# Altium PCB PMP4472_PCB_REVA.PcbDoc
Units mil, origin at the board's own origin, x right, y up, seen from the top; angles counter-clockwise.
Board outline 3307.09 x 3307.09 mil, 2 copper layers (TOP, BOTTOM), stack 10.4 mil thick; 66 components, 41 nets, 173 pads, 20 vias.
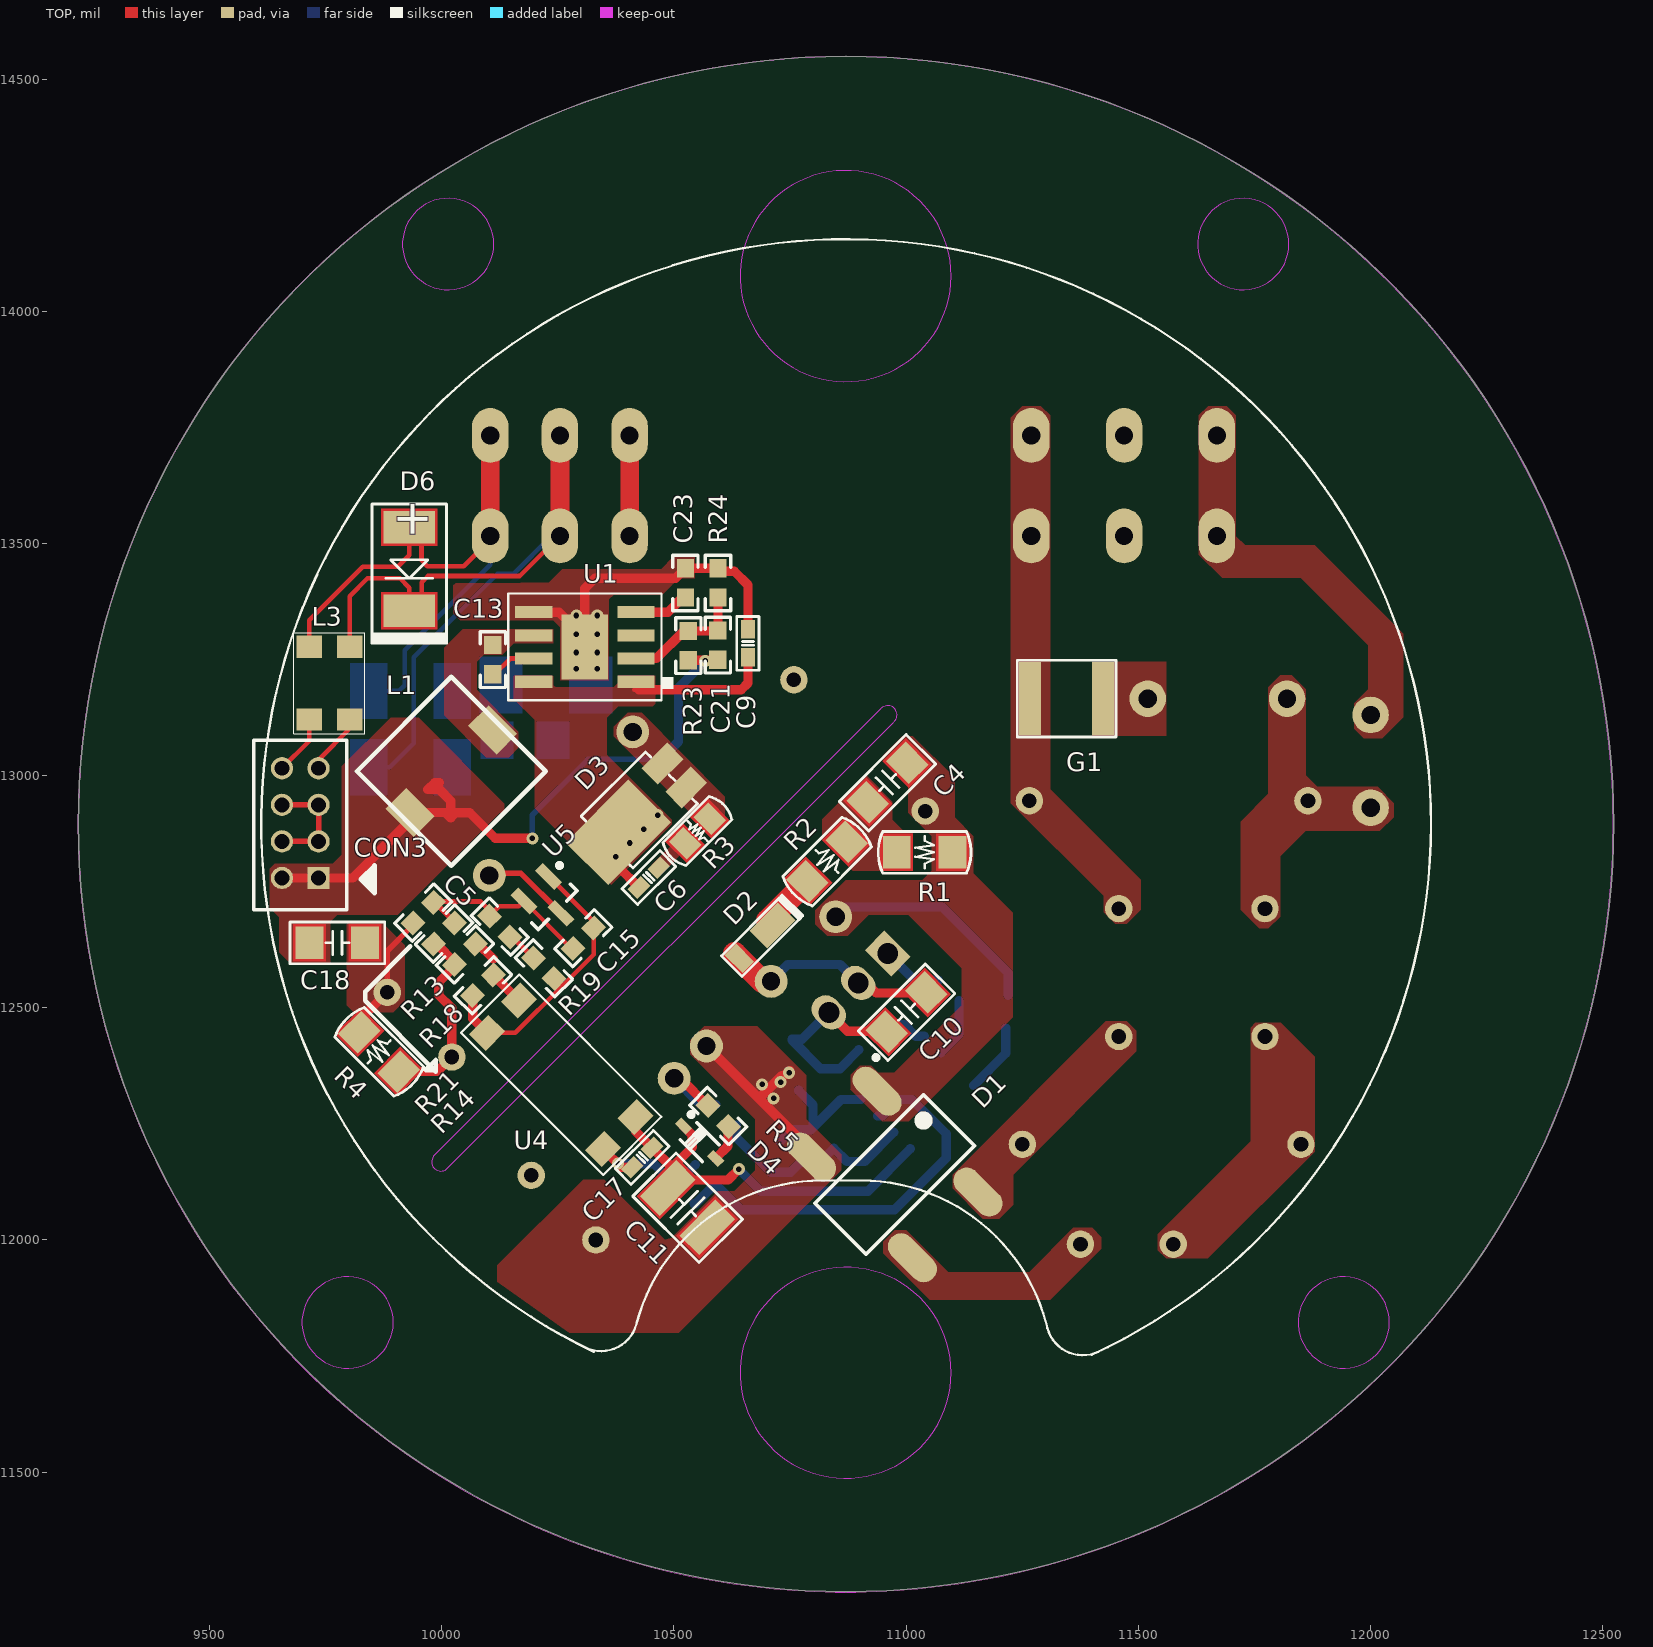
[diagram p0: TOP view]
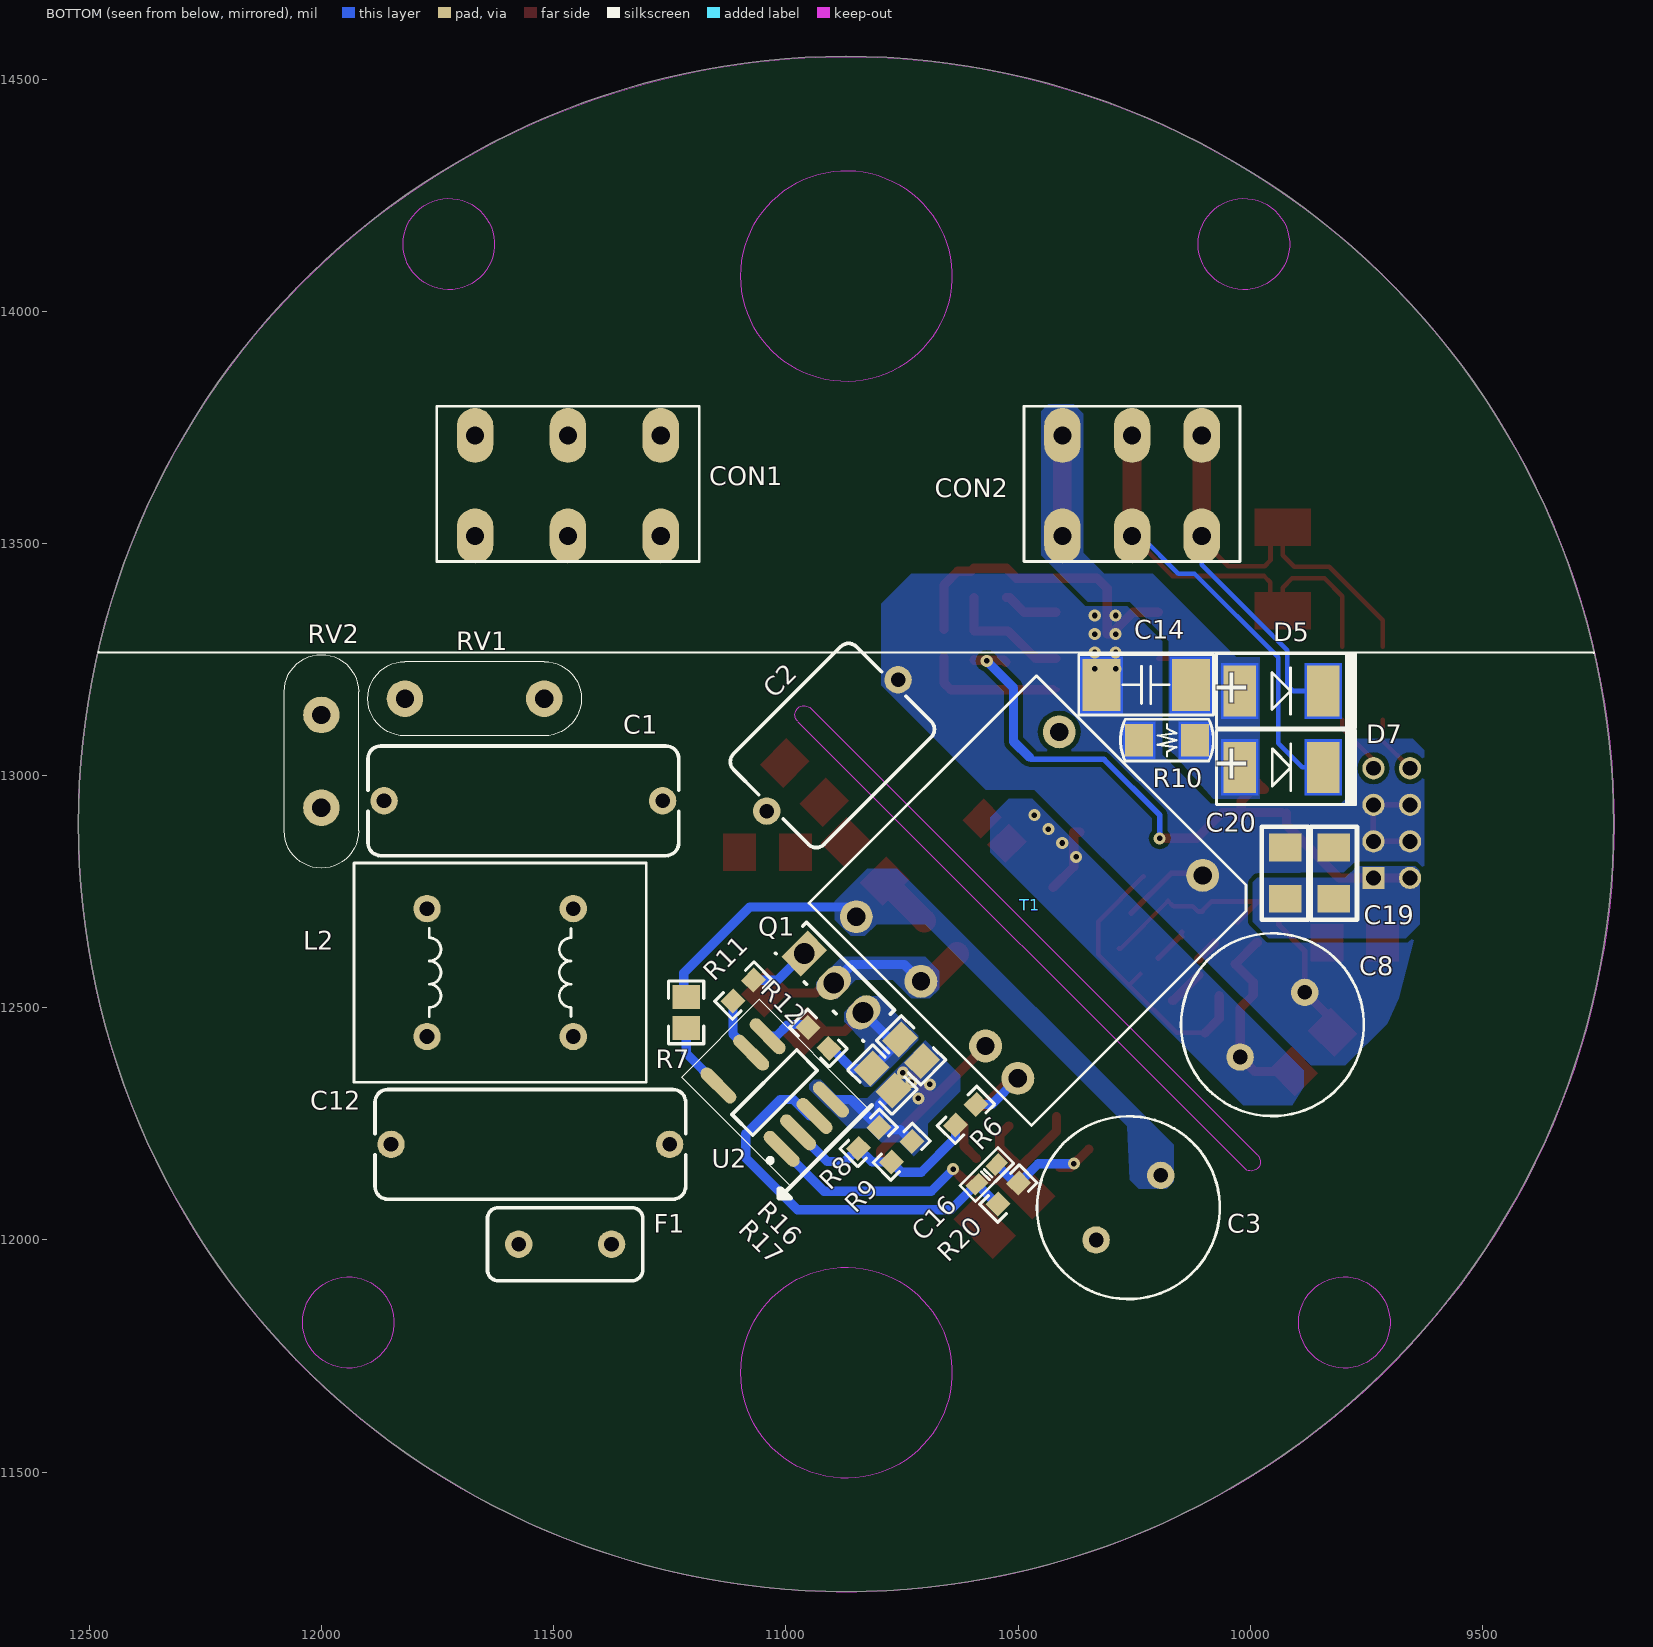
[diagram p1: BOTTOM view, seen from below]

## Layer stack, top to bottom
TOP: signal copper 1.2
Dielectric: core 8, FR-4, Dk 4.5
BOTTOM: signal copper 1.2

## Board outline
10870.72,11242.32 cw(c10870.72,12895.86) 9217.17,12895.86 cw(c10870.72,12895.86) 10870.72,14549.41 cw(c10870.72,12895.86) 12524.26,12895.86 cw(c10870.72,12895.86)

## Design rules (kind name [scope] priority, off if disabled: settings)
Clearance [All] p1: gap=10
PlaneClearance [All] p1: clearance=10
PlaneConnect [All] p1: planeconnectstyle=Direct reliefexpansion=20 reliefentries=4 reliefconductorwidth=10 reliefairgap=10
PolygonConnect [All] p1: connectstyle=Direct reliefconductorwidth=10 reliefentries=4 polygonreliefangle="90 Angle" airgapwidth=10
RoutingVias [All] p1: holewidth=12 width=28 viastyle="Through Hole" minholewidth=10 minwidth=20 maxholewidth=20 maxwidth=50
SilkscreenOverComponentPads [All] p1: minsilkscreentomaskgap=10
SolderMaskExpansion [All] p1: expansion=4
Width [All] p1: maxlimit=60 minlimit=10 preferedwidth=20
25 further rules are at their usual default settings.

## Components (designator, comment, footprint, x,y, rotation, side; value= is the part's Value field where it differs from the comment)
C1 "100nF" CAPRR_15D24_17D0X6D0X12D0 11565.72,12945.86 r180 bottom
C2 "2.2nF" CAPRR_10D16_9D5X7D0X9D5 10900,13065 r315 bottom
C3 "15uF" CAPAE1000X1600_TH 10262.34,12069.48 r135 bottom
C4 "220pF" C1206#1 10960,12985 r225 top
C5 "Cap" 0603 10125,12675 r315 top
C6 "1nF" C0603 10445.72,12780.86 r225 top
C8 "1500uF" CAPAE1000X1600_TH 9952.19,12463.56 r315 bottom
C9 "100nF" C0603 10660,13285 r90 top
C10 "33pF" C1206#1 11001.15,12490.6 r225 top
C11 "10uF" C1210 10529.42,12069.38 r315 top
C12 "100nF" CAPRR_15D24_17D0X6D0X12D0 11550.72,12205.86 r180 bottom
C13 "06031C331JAT2A" 0603 10110,13250 r270 top
C14 "1nF" C1812 10224.39,13195.62 r0 bottom
C15 "Cap" 0603 10305,12650 r45 top
C16 "47nF" C0603 10567.08,12140.65 r135 bottom
C17 "NA" C0603 10432.08,12177.15 r45 top
C18 "1206" C1206#1 9775,12640 r180 top
C19 "1206" C1206#2 9820,12790 r270 bottom
C20 "1206" C1206#2 9925,12790 r270 bottom
C21 "06031C331JAT2A" 0603 10594.74,13281.14 r270 top
C23 "06031C331JAT2A" 0603 10525,13415 r90 top
CON1 "5.08mm LSF-SMT-C3P6" CON_LSF-SMT-5D08-C3P6-180 11469.62,13628.56 r180 bottom
CON2 "3.81mm LSF-SMT-C3P6" CON_LSF-SMT-3D81-C3P6-180 10254.62,13628.56 r180 bottom
CON3 "2.00mm 2x4 TH HEADER 7.4MM" CON_2D00_2X4_TH 9695.22,12893.36 r180 top
D1 "DF06S" DIODE_DFS 10975.72,12140.86 r315 top
D2 "DFLR1600" POWERDI123 10690,12655 r45 top
D3 "PDS1040L" POWERDI5 10425.72,12925.86 r135 top
D4 "BAS21HT1G" SOD-323 10555.24,12210.44 r315 top
D5 "P6SMB6.8A" SMB 9932.99,13182.37 r180 bottom
D6 "P6SMB6.8CA" SMB 9930,13445 r270 top
D7 "P6SMB6.8A" SMB 9932.67,13017.9 r180 bottom
F1 "1A" F5D08_8D5X4D0X8D0MM 11475.72,11990.86 r0 bottom
G1 "SG600Q" G4532 11345.72,13165.86 r180 top
L1 "3.3uH" "Inductor 744778003" 10020.63,13009.57 r225 top
L2 "10mH" L16D0X12D0X17D5MM 11615.72,12575.86 r90 bottom
L3 "SRF4532-101Y" L4D5X3D2X2D8MM 9758.05,13199.24 r90 top
Q1 "FQP6N70" TO-251AB 10897.21,12553.47 r225 bottom
R1 "300K" R1206 11040,12835 r180 top
R2 "300R" R1206 10830,12815 r225 top
R3 "15R" R0805 10550.72,12880.86 r225 top
R4 "1.5K" R1206 9865,12405 r315 top
R5 "22R" 0603 10595.47,12266.95 r135 top
R6 "470K 1%" 0603 10612.48,12269.41 r315 bottom
R7 "Res1" 0805 11215,12490 r90 bottom
R8 "360K 1%" 0603 10821.92,12219.65 r135 bottom
R9 "47K 1%" 0603 10750.74,12189.92 r135 bottom
R10 "300R" R1206 10179.23,13076.4 r0 bottom
R11 "Res1" 0603 11091.95,12537.15 r135 bottom
R12 "Res1" 0603 10930,12435 r225 bottom
R13 "Res1" 0603 10050,12615 r225 top
R14 "Res1" 0603 10005,12660 r225 top
R16 "Res1" 0805 10730.55,12408.53 r45 bottom
R17 "Res1" 0805 10792.31,12345.23 r45 bottom
R18 "Res1" 0603 10088.74,12548.37 r45 top
R19 "Res1" 0603 10220,12585 r315 top
R20 "Res1" 0603 10520.97,12099.93 r315 bottom
R21 "Res1" 0603 9960,12705 r45 top
R23 "CRCW06031K00FKEA" 0603 10531.16,13280.24 r90 top
R24 "CRCW06031K00FKEA" 0603 10595,13415 r270 top
RV1 "MOV-10D681K" MOV-10D 11670.72,13165.86 r90 bottom
RV2 "MZ2-390N" PTC-T5MMD10MM 12000.72,13030.86 r180 bottom
T1 "TRNSFMR_EPC17" EPC17 10465.72,12730.86 r225 bottom
U1 "TPS54228D" DDA-8 10308.23,13277.26 r180 top
U2 "UCC28740" SOIC-7 11034.94,12170.33 r45 bottom
U4 "FOD817" OPTOCOUPLER 10097.18,12446.15 r315 top
U5 "TL431AIDBZ" SOT-23 10230,12730 r315 top

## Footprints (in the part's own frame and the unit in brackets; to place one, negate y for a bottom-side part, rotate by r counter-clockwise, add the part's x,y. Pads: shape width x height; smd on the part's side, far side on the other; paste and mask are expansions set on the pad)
0603 [mm] "0603 from SM-752 data"
  rect 1x0.95 smd: 1(-0.8,0) 2(0.8,0)
  silkscreen extent -1.52,-0.69 1.52,0.69, body extent -0.87,-0.47 0.87,0.47, height 0.85
0805 [mm] "0805 from SM-752 data"
  rect 1.3x1.5 smd: 1(-0.85,0) 2(0.85,0)
  silkscreen extent -1.72,-0.97 1.72,0.97, body extent -1.1,-0.72 1.1,0.72, height 1.1
C0603 [mil] "C0603"
  rect 40x30 smd: 1(-30,0.5) 2(30,0.5)
  silkscreen extent -58,-23 58,24
C1206#1 [mil] "C1206"
  rect 60x70 smd: 1(-60,0) 2(60,0)
  TOP region: -95,40 -25,40 -25,-40 -95,-40
  TOP region: 25,40 95,40 95,-40 25,-40
  silkscreen extent -102,-45 102,45
C1206#2 [mil]
  rect 60x70 smd: 1(-55,0) 2(55,0)
  silkscreen extent -100,-50 100,50
C1210 [mil] "C1210"
  rect 60x110 smd: 1(-60,0) 2(60,0)
  TOP region: -95,60 -25,60 -25,-60 -95,-60
  TOP region: 25,60 95,60 95,-60 25,-60
  silkscreen extent -101,-66 101,66
C1812 [mil] "C1812"
  rect 82x112 smd: 1(-96.46,0) 2(96.46,0)
  TOP region: 50.5,61 142.5,61 142.5,-61 50.5,-61
  TOP region: -142.5,61 -50.5,61 -50.5,-61 -142.5,-61
  silkscreen extent -145,-65 145,65
CAPAE1000X1600_TH [mm] "CAPAE1000X1600_TH"
  round 1.5 / inner round 1.524 / far side round 1.5 hole 0.8: 1(2.5,0) 2(-2.5,0)
  silkscreen extent -5,-5 5,5
CAPRR_10D16_9D5X7D0X9D5 [mm] "CAPRR_10D16_9D5X7D0X9D5"
  round 1.5 / inner round 1.524 / far side round 1.5 hole 0.8: 1(5.08,0) 2(-5.08,0)
  silkscreen extent -4.75,-3.5 4.75,3.5
CAPRR_15D24_17D0X6D0X12D0 [mm] "CAPRR_15D24_17D0X6D0X12D0"
  round 1.5 / inner round 1.524 / far side round 1.5 hole 0.8: 1(7.62,0) 2(-7.62,0)
  silkscreen extent -8.5,-3 8.5,3
CON_2D00_2X4_TH [mil] "CON_2D00_2X4_TH"
  rect 48x48 / inner round 60 / far side rect 48x48 hole 32: 1(-39.4,113.7)
  round 48 / inner round 60 / far side round 48 hole 32: 2(39.4,113.7) 3(-39.4,34.9) 4(39.4,34.9) 5(-39.4,-43.8) 6(39.4,-43.8) 7(-39.4,-122.6) 8(39.4,-122.5)
  silkscreen extent -160,-183 100,182
CON_LSF-SMT-3D81-C3P6-180 [mm] "CON_LSF-SMT-3D81-C3P6-180"
  oval 2x3 / inner round 1.524 / far side oval 2x3 hole 1: 1(3.81,2.65) 2(3.81,-2.85) 3(0,2.65) 4(0,-2.85) 5(-3.81,2.65) 6(-3.81,-2.85)
  silkscreen extent -5.91,-4.25 5.91,4.98
CON_LSF-SMT-5D08-C3P6-180 [mm] "CON_LSF-SMT-5D08-C3P6-180"
  oval 2x3 / inner round 1.524 / far side oval 2x3 hole 1: 1(5.08,2.65) 2(5.08,-2.85) 3(0,2.65) 4(0,-2.85) 5(-5.08,2.65) 6(-5.08,-2.85)
  silkscreen extent -7.18,-4.25 7.18,5.04
DDA-8 [mil]
  rect 80x26 smd: 1(-110,75) 2(-110,25) 3(-110,-25) 4(-110,-75) 5(110,-75) 6(110,-25) 7(110,25) 8(110,75)
  rect 100x140 smd: 9(0,0)
  silkscreen extent -190,-115 165,115
DIODE_DFS [mm] "DIODE_DFS"
  oval 3.2x1.45 smd: 1(-3.9,2.54) 2(-3.9,-2.54) 3(3.9,-2.54) 4(3.9,2.54)
  silkscreen extent -5.37,-4.2 1.97,4.2
EPC17 [mm] "EPC17"
  round 1.8 / inner round 1.524 / far side round 1.8 hole 1: 1(5.55,7.5) 4(-5.55,7.5) 5(-6.25,-7.5) 7(-1.25,-7.5) 9(3.75,-7.5) 10(6.25,-7.5)
  silkscreen extent -8.6,-8.8 8.6,8.8
F5D08_8D5X4D0X8D0MM [mm] "F5D08_8D5X4D0X8D0MM"
  round 1.5 / inner round 1.524 / far side round 1.5 hole 0.8: 1(2.54,0) 2(-2.54,0)
  silkscreen extent -4.25,-2 4.25,2
G4532 [mm] "G4532"
  rect 1.2x4 smd: 1(-2,0) 2(2,0)
  silkscreen extent -2.7,-2.1 2.7,2.1
"Inductor 744778003" [mm]
  rect 1.6x2.2 smd: 1(-3.2,0) 2(3.2,0)
  silkscreen extent -3.65,-3.65 3.65,3.65
L4D5X3D2X2D8MM [mil] "L4D5X3D2X2D8MM"
  rect 48x55 smd: 1(-78.5,-43.5) 2(78.5,-43.5) 3(78.5,43.5) 4(-78.5,43.5)
  silkscreen extent -108,-76 108,76
L16D0X12D0X17D5MM [mm] "L16D0X12D0X17D5MM"
  round 1.5 / inner round 1.524 / far side round 1.5 hole 0.8: 1(3.5,4) 2(-3.5,4) 3(-3.5,-4) 4(3.5,-4)
  silkscreen extent -6,-8 6,8
MOV-10D [mil] "MOV-10D"
  round 78.7 / inner round 60 / far side round 78.7 hole 39.4: 1(0,150) 2(0,-150)
  silkscreen extent -80,-230 80,230
OPTOCOUPLER [mm]
  rect 1.3x1.5 smd: 1(0,2.5) 2(0,0) 3(9,0) 4(9,2.5)
  silkscreen extent -1,-1 10,3.5
POWERDI5 [mil] "POWERDI5"
  rect 50x78 smd: 1(-36.76,-105.87) 2(35.68,-105.87)
  rect 130x192 smd: 3(-1.76,66.13)
  silkscreen extent -79,-99 79,98
POWERDI123 [mm] "POWERDI123"
  rect 0.9x1.4 smd: 1(-1.75,0)
  rect 2.2x1.4 smd: 2(0.8,0)
  silkscreen extent -2.35,-0.8 2.35,0.8
PTC-T5MMD10MM [mil] "PTC-T5MMD10MM"
  round 78.7 / inner round 60 / far side round 78.7 hole 39.4: 1(0,100) 2(0,-100)
  silkscreen extent -80,-230 80,230
R0805 [mil] "R0805"
  rect 45x55 smd: 1(-37.5,0) 2(37.5,0)
  TOP region: -65,32.5 -10,32.5 -10,-32.5 -65,-32.5
  TOP region: 10,32.5 65,32.5 65,-32.5 10,-32.5
  silkscreen extent -80,-35 80,35
R1206 [mil] "R1206"
  rect 60x70 smd: 1(-60,0) 2(60,0)
  TOP region: 25,40 95,40 95,-40 25,-40 25,40
  TOP region: -95,40 -25,40 -25,-40 -95,-40 -95,40
  silkscreen extent -100,-45 100,45
SMB [mil] "SMB"
  rect 70x110 smd: 1(-90,0) 2(90,0)
  TOP region: -130,60 -50,60 -50,-60 -130,-60
  TOP region: 50,60 130,60 130,-60 50,-60
  silkscreen extent -140,-80 160,80
SOD-323 [mm] "SOD-323"
  rect 0.85x0.5 smd: 1(1.25,0) 2(-1.25,0)
  silkscreen extent -1.52,-0.65 0.85,0.87
SOIC-7 [mm]
  oval 2.5x0.7 smd: 1(0.003,-0.928) 2(0.003,-2.198) 3(0.003,-3.468) 4(0.003,-4.738) 5(4.903,-4.738) 6(4.903,-3.468) 7(4.903,-0.928)
  silkscreen extent -1.75,-5.83 6.65,0.17, body extent 0.45,-5.33 4.45,-0.33, height 1.75
SOT-23 [mm] "SOT23, 3-Leads, Body 2.9x1.3mm, Pitch 0.95mm, Lead Span 2.5mm, IPC Medium Density"
  rect 1.5x0.6 smd: 1(-0.95,0.95) 2(-0.95,-0.95) 3(0.95,0)
  silkscreen extent -1.07,-1.5 0.7,1.92, body extent -1.16,-1.45 1.21,1.45, height 1
TO-251AB [mil] "IPAK"
  rect 60x80 hole 45: 1(-89.76,0)
  oval 60x80 hole 45: 2(0,0) 3(89.76,0)
  silkscreen extent -134,-43 134,51, body extent -128,-39 128,51, height 380

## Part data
C1 C12: library part "CAP NP", "CAP;100nF,CER,275V(UL CSA 250V),10%,CBB,17x6x12,TH"
C2: library part "CAP NP", "CAP;2.2nF,CER,1KV,5%,Z5U,9.5x7.0x9.5,TH"
C3: library part "CAP POL", "CAP;15uF,ALUM,400V,20%,ALUM,C10X16,DIP"
C4: library part "CAP NP 1206", "CAP;220pF,CER,630V,5%,COG,1206,SMD"
C5 C15: "Capacitor"
C6 C16 C17: library part "CAP NP 0603", "CAP;1nF,CER,100V,10%,X7R,0603,SMD"
C8: library part "CAP POL", "CAP;1500uF,ALUM,6.3V,20%,ALUM,C10X12,DIP"
C9: library part "CAP NP 0603", "CAP;100nF,CER,50V,10%,X7R,0603,SMD"
C10: library part "CAP NP 1206", "CAP;33pF,CER,1KV,5%,COG,1206,SMD"
C11: library part "CAP NP 1210", "CAP;10uF,CER,35V,10%,X5R,1210,SMD"
C13 C21 C23: "CAP, CERM, 330pF, 100V, +5/%, X7R, 0603"
C14: library part "CAP NP 1812", "CAP;1nF,CER,2KV,10%,X7R,1812,SMD"
C18 C19 C20: library part C1206, "Capacitor, Ceramic, 4V, X5R, 10%"
CON1: library part LSF-SMT-C3P6, "CONN HEADER;2x3P,5.08mm,VERT,DIP,LSF-SMT,TIN"
CON2: library part LSF-SMT-C3P6, "CONN HEADER;2x3P,3.81mm,VERT,DIP,LSF-SMT,TIN"
CON3: library part CON8A, "CONN HEADER;2x4P,2.00mm 7.4mm high,VERT,DIP,PIN,TIN"
D1: library part BRIDGE_SMD, "BRIDGE;BRIDGE RECTIFIER,600V,1A,DFS,4PIN"
D2: library part DIODE, "DIODE;GLASS PASSIVATED,600V,1A,POWERDI123,SMD"
D3: library part "DIODE POWERDI5", "DIODE;SCHOTTKY,40V,10A,POWERDI5,SMD"
D4: library part DIODE, "DIODE;HIGH VOLTAGE SWITCHING DIODE,250V,200mA,SOD323,SMD"
D5 D7: library part "DIODE TVS UNI-DIR", "DIODE TVS;6.45V,7.14V,600W,UNI-DIR,SMA,SMD"
D6: library part "DIODE TVS BI-DIR", "DIODE TVS;5.8V,6.8V,600W,BI-DIR,SMB,SMD"
F1: library part FUSE, "FUSE;1A,250V,Time-Lag,8.5x4x8.0,TH"
G1: library part GDT_SINGLE, "DIODES;gas discharge tube,-40C/+85C,SMD"
L1: library part Inductor, "Inductor, [Technology], [Material], xxuH, xxA, x.xx ohm, [MountType]"
L2: library part "COMMON MODE CHOKE CM14", "IND;10mH,?,?mohm,1A,L16D0X12D0X17D5MM,TH"
L3: library part "COMMON MODE CHOKE CM14", "IND;2Kohm 10MHz,SRF4532-101Y,SMD,SHIELDED,FERRITE"
Q1: library part Mosfet
R1: library part R, "RES;300Kohm,1/4W,5%,1206,SMD"
R2 R10: library part R, "RES;300ohm,1/4W,5%,1206,SMD"
R3: library part R, "RES;15ohm,1/8W,5%,0805,SMD"
R4: library part R, "RES;1.5Kohm,1/4W,5%,1206,SMD"
R5: library part R, "RES;22ohm,1/10W,5%,0603,SMD"
R6 R9: library part R, "RES;47Kohm,1/10W,1%,0603,SMD"
R7 R11 R12 R13 R14 R16 R17 R18 R19 R20 R21: "Resistor"
R8: library part R, "RES;360Kohm,1/10W,1%,0603,SMD"
R23 R24: "RES, 1.00k ohm, 1%, 0.1W, 0603"
RV1: library part VARISTOR_Dup1, "MOV;MOV-10D681K,31V MOV,-40C/+85C,MOV-10D,2PIN"
RV2: library part VARISTOR, "PTC;MZ2-390N,,-40C/+85C,PTC-T5MMD10MM,2PIN"
T1: "FLYBACK TRANSFORMER;8W,3.3V,2.2A,EPC17,TH,SHIELDED"
U1: "Buck Step Down Regulator with 4.5 to 18 V Input and 0.76 to 7 V Output, -40 to 85 degC, 8-Pin SOIC (D), Green (RoHS & no Sb/Br)"
U4: library part Optoisolator1, "4-Pin Phototransistor Optocoupler"
U5: "PRECISION PROGRAMMABLE REFERENCE, DBZ0003A"

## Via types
v1: diameter 26, hole 12, TOP to BOTTOM, 20 vias

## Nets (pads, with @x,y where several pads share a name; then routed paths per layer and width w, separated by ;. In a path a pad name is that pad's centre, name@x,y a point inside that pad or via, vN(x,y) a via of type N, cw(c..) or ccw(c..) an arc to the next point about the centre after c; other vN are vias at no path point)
3V3_FB: C21.1 R23.2 R24.2 U1.2 | length 272.5
  TOP w20: U1.2 10462.26,13252.26 10521.73,13311.73 R23.2 10593.83,13311.73 C21.1 10595,13312.9 R24.2
3V3_SW: C13.1 L1.1 U1.6 | length 10.1
  TOP w20: L1.1@10100.28,13097.8 L1.1@10110.41,13097.8
EX_RS485_A: CON2.3 CON2.4 D6.2 D7.2 L3.2 | length 1681
  TOP w10: L3.2 9801.55,13386.55 9840,13425 9910,13425 9930,13405 D6.2@9930,13356.3 ; D6.2 D6.2@9930,13356.3 ; CON2.4 10168.26,13430 9970.41,13430 9957,13416.59 9957,13356.3 D6.2@9930,13356.3
  TOP w40: CON2.4 CON2.3
  BOTTOM w10: D7.2 9887.9,13017.9 9940,13070 9940,13255 10120,13435 10155,13435 10236.36,13516.36 CON2.4
EX_RS485_B: CON2.1 CON2.2 D5.2 D6.1 L3.3 | length 1369.7
  TOP w10: L3.3 9714.55,13334.55 9830,13450 9905,13450 9930,13475 D6.1 ; D6.1@9931.27,13533.73 9933.17,13535.63 9956.34,13535.63 9956.34,13463.63 9968.73,13451.23 10046.94,13451.23 10104.62,13508.9 CON2.2
  TOP w40: CON2.2 CON2.1
  BOTTOM w10: D5.2 9907.37,13182.37 9920,13195 9920,13270 10104.62,13454.62 CON2.2
FB: C16.1 R20.2 U2.3 | length 874.9
  BOTTOM w20: R20.2 10546.52,12077.66 C16.1 10590.21,12119.79 10645,12065 10975,12065 11086.44,12176.44 11086.44,12228.66 11012.64,12302.46 10984.05,12302.46 10948.55,12266.96 U2.3
GND: C2.2 C8.2 C9.2 C14.2 C18.1 C19.1 C20.1 C23.2 CON3.3 CON3.4 CON3.5 CON3.6 R4.1 R10.2 R21.1 R24.1 T1.1 U1.5 U1.9 U5.3 | length 1420.6
  TOP w12: CON3.4 CON3.3 CON3.5 CON3.6 ; C8.2 9882.59,12622.59 9939.02,12679.02 R21.1@9939.02,12684.26 ; T1.1 10107.27,12790 10170,12790 U5.3
  TOP w20: R4.1 9822.57,12473.14 C8.2 ; U1.5 10252.74,13352.26 10300,13305 10308.23,13305 10308.23,13403.23 10330,13425 10503.5,13425 C23.2 R24.1 10601.5,13440 10630,13440 10659.5,13410.5 C9.2
  other v1: 10290,13230 10335,13230 10290,13265.3 10335,13265.32 10290,13305 10335,13305 10290,13345 10335,13345
GND_485_SHIELD: C14.1 CON2.5 CON2.6 D5.1 D7.1 R10.1 | length 216.5
  TOP w40: CON2.6 CON2.5
GND_HV: C3.2 C11.2 D1.2 R8.2 R9.2 R16.1 R17.1 T1.9 U2.4 | length 774.5
  TOP w20: C11.2@10548.09,11999.88 C11.2@10575.17,12026.96 ; T1.9 10796.43,12191.35 D1.2 ; 10683.27,12304.51 10732.74,12353.99 10737.77,12353.99 10748.78,12365 10750,12365 10748.03,12363.03 v1(10748.03,12360.05)
  BOTTOM w20: R9.2 10753.87,12237.6 10795.33,12237.6 R8.2 ; R17.1@10768.65,12323.1 R17.1 10799.65,12290.57 R8.2 ; U2.4 10860.05,12302.32 R8.2
  other v1: 10715,12305 10690,12335 10730,12340
NetC1_1: C1.1 CON1.1 CON1.2 G1.2 L2.4
NetC1_2: C1.2 L2.1 RV1.1 RV2.2
NetC4_2: C4.2 R1.2 R2.1
NetC5_1: C5.1 C15.1 R14.1 R21.2 U5.2 | length 425.7
  TOP w10: R21.2@9983.56,12728.8 10083.8,12728.8 C5.1@10105.34,12707.27 ; C5.1@10102.73,12707.27 C5.1@10105.34,12707.27 ; C15.1 10279.38,12627.73 U5.2 10165.74,12718.64 10123.64,12718.64 10112.27,12707.27 C5.1@10105.34,12707.27
  TOP w12: R21.2@9983.56,12728.8 10027.28,12685.09 R14.1@10028.72,12685.09
NetC5_2: C5.2 R19.1 | length 69.3
  TOP w12: C5.2 10152.27,12652.73 R19.1
NetC6_1: C6.1 R3.2
NetC10_1: C10.1 D2.1 Q1.2 T1.7 | length 513.8
  TOP w20: Q1.2 10914.31,12553.46 10935.99,12531.79 11042.3,12531.79 C10.1@11050.81,12540.3
  TOP w50: D2.1@10631.28,12616.28 10690.69,12556.87 T1.7
  BOTTOM w20: T1.7@10683.57,12556.87 T1.7 10745.5,12593.06 10857.62,12593.06 Q1.2
NetC10_2: C10.2 Q1.3 R12.2 R16.2 R17.2 | length 443.1
  TOP w20: Q1.3 10874.05,12449.68 10960.19,12449.68 C10.2@10965.95,12455.45
  BOTTOM w20: Q1.3 10775.94,12432.2 R16.2 10754.21,12430.66 R17.2 10857.66,12368.9 R12.2@10898.47,12409.71
NetC12_1: C12.1 D1.4 L2.3
NetC12_2: C12.2 F1.1 L2.2
NetC13_2: C13.2 U1.7 | length 102.2
  TOP w10: C13.2 10113.5,13218.5 10147.26,13252.26 U1.7
NetC15_2: C15.2 R18.1 R19.2 U4.2 U5.1 | length 635.6
  TOP w10: U4.2 10158.6,12446.15 10260,12547.55 ; U5.1 10327.27,12685.62 C15.2 10327.27,12614.82 10260,12547.55 ; R19.2@10237.27,12572.73 10260,12550 10260,12547.55
  TOP w20: R18.1 10066.47,12476.85 U4.2
NetC16_2: C16.2 C17.1 R20.1 U4.3 | length 279.5
  TOP w20: U4.3 10387.04,12156.29 C17.1
  BOTTOM w20: v1(10379.77,12164.31) 10456.59,12164.31 R20.1 10506.21,12122.2 C16.2
NetCON1_5: CON1.5 CON1.6 RV2.1
NetD1_3: D1.3 F1.2
NetD2_2: D2.2 R2.2 | length 120.6
  TOP w50: D2.2@10702.27,12687.27 R2.2
NetD3_1: D3.1 D3.2 R3.1 T1.4
NetD4_1: D4.1 R5.1 | length 81.1
  TOP w20: D4.1 10616.68,12202.29 R5.1@10616.68,12245.74
NetG1_1: G1.1 RV1.2
NetQ1_1: Q1.1 R11.2 | length 132.8
  BOTTOM w20: Q1.1 11018.19,12559.42 R11.2
NetR5_2: R5.2 R6.1 T1.10 | length 211.6
  TOP w20: T1.10 10514.35,12348.08 R5.2@10574.26,12288.17
  BOTTOM w20: T1.10 10556.91,12291.69 R6.1
NetR7_1: R7.1 U2.7 | length 152.6
  BOTTOM w20: U2.7 11215,12402.06 R7.1
NetR11_1: R11.1 U2.6 | length 127.8
  BOTTOM w20: U2.6 11114.22,12442.71 R11.1
NetR12_1: R12.1 U2.5 | length 100.5
  BOTTOM w20: R12.1 10958.94,12463.94 10995.45,12463.94 11020.66,12438.73 U2.5
NetR13_1: R13.1 R18.2 U4.1 | length 126.5
  TOP w20: R13.1@10077.05,12639.28 10111.02,12605.31 ; R18.2 10165.91,12515.74 U4.1
RS485_A: CON3.7 L3.1 | length 132.5
  TOP w10: CON3.7 9734.62,13034.62 9801.55,13101.55 L3.1
RS485_B: CON3.8 L3.4 | length 129.2
  TOP w10: CON3.8 9714.55,13074.6 L3.4
SS: C23.1 U1.4 | length 119.7
  TOP w20: U1.4 10487.26,13352.26 10518.5,13383.5 C23.1
VCC: C11.1 C17.2 D4.2 U2.1 U4.4 | length 927.7
  TOP w20: U4.4 10417.33,12234.33 C17.2 10495.83,12155.83 10512.61,12139.04 10512.61,12137.43 C11.1@10504.09,12128.91 ; C11.1 10487,12147 10539.49,12199.49 10539.49,12223.81 10540.68,12225 D4.2 ; C11.1@10495.54,12120.36 C11.1@10504.09,12128.91 ; v1(10639.89,12152.39) 10616.4,12128.91 C11.1@10504.09,12128.91
  BOTTOM w20: v1(10639.89,12152.39) 10687.29,12105 10917.94,12105 U2.1
VCC_300V: C2.1 C3.1 C4.1 D1.1 R1.1 R7.2 T1.5 | length 487.2
  BOTTOM w20: T1.5 10869.38,12716.94 11078.06,12716.94 11220.22,12574.78 R7.2@11220.22,12526.8
VDD_3V3_MAIN: C18.2 C19.2 C20.2 C21.2 CON3.1 CON3.2 L1.2 R23.1 | length 1461.3
  TOP w20: CON3.2 CON3.1 9808.23,12779.66 9922.11,12893.54 L1.2@9922.11,12919.63 ; L1.2 10007.65,12920.49 10019.46,12908.68 10019.46,12909.46 ; 9995,12985 9985,12985 9970,12970 9995,12970 10019.46,12945.54 10019.46,12909.46 ; v1(10195,12865) 10115,12865 10060,12920 10030,12920 10019.46,12909.46 ; R23.1@10526.45,13244.03 R23.1 10593.83,13248.74 C21.2
  BOTTOM w12: v1(10195,12865) 10195,12915 10315,13035 10471.26,13035 10476.26,13040
  BOTTOM w20: 10476.26,13040 10510,13073.74 10510,13189.6 v1(10567.54,13247.14)
VDD_5V_MAIN: C6.2 C8.1 C9.1 D3.3 R4.2 R13.2 R14.2 U1.1 U1.8 | length 879.2
  TOP w10: 10415,13185 10425,13185
  TOP w20: R4.2 9990.39,12362.57 C8.1 10021.79,12499.43 10021.5,12499.43 9993.62,12527.31 9993.62,12554.99 10032.51,12593.88 9985.84,12640.55 R14.2@9984.18,12640.55 ; D3.3@10366.92,12877.86 D3.3 10380.2,12803.95 C6.2 ; 10425,13185 10645,13185 10659.5,13199.5 C9.1
  other v1: 10375,12825 10405,12855 10435,12885 10465,12915
VS: R6.2 R8.1 R9.1 U2.2 | length 456.1
  BOTTOM w20: R6.2 10634.75,12219.76 10708.55,12145.96 10751.32,12145.96 R9.1 10814.47,12167.65 R8.1 10872.71,12168.86 10911.09,12168.86 U2.2
pads on no net: CON1.3 CON1.4 U1.3

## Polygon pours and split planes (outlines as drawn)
NetC12_2 on TOP "TOP-N53840" (solid, pour order 29): 11752.5,12467.5 11807.5,12467.5 11880,12395 11880,12190 11650,11960 11560,11960 11542.5,11977.5 11542.5,12012.5 11742.5,12212.5 11742.5,12457.5
3V3_SW on TOP "TOP-No Net 1" (solid, pour order 34): 10240,13315 10045,13315 10005,13275 10005,13130 10095,13040 10145,13040 10165,13060 10165,13095 10075,13185 10075,13245 10090,13260 10130,13260 10155,13285 10240,13285
GND on TOP "TOP-No Net 7" (solid, pour order 50): 9795,12580 9795,12680 9800,12685 9870,12685 9885,12670 9895,12660 9920,12635 9920,12515 9900,12495 9895,12490 9820,12490 9810,12490 9795,12505 9795,12675
NetC4_2 on TOP "TOP-No Net 6" (solid, pour order 49): 10885,12795 11015,12795 11015,12875 11000,12875 10970,12905 10970,12943.43 10970.61,12944.04 10914.04,13000.61 10819.39,12905.96 10819.39,12860.96
NetD3_1 on TOP "TOP-N01324" (solid, pour order 42): 10370.72,13084.9 10577.74,12877.88 10610,12910 10610,12955 10430.72,13135.86 10400.72,13135.86 10370.72,13105.86
VDD_3V3_MAIN on TOP "TOP-No Net" (solid, pour order 33): 9785,12830 9785,13020 9890,13125 9950,13125 10135,12940 10135,12920 10125,12920 9905,12700 9775,12700 9760,12685 9760,12595 9675,12595 9650,12620 9650,12695 9630,12715 9630,12800 9640,12810 9765,12810
GND on TOP "TOP-No Net 3" (solid, pour order 37): 10255,13205 10255,13320 10240,13335 10040,13335 10025,13350 10025,13410 10030,13415 10230,13415 10260,13445 10472.73,13445 10497.73,13470 10545,13470 10545,13425 10510,13425 10475,13390 10370,13390 10360,13380 10360,13205
VDD_5V_MAIN on TOP "TOP-No Net 2" (solid, pour order 35): 10365,12765 10200,12930 10200,13120 10155,13165 10155,13215 10238.54,13215 10238.9,13215.36 10240,13214.26 10240,13195 10245,13190 10370,13190 10380,13200 10380,13215 10460,13215 10460,13155 10455,13150 10380,13150 10355,13125 10355,13045 10495,12905 10495,12895
NetCON1_5 on TOP "TOP-N27083" (solid, pour order 38): 11630.72,13775.86 11630.72,13475.86 11680.72,13425.86 11850.72,13425.86 11995.72,13280.86 11995.72,13185.86 11965.72,13155.86 11965.72,13100.86 11985.72,13080.86 12025.72,13080.86 12070.72,13125.86 12070.72,13305.86 11880.72,13495.86 11730.72,13495.86 11710.72,13515.86 11710.72,13775.86 11690.72,13795.86 11650.72,13795.86 11630.72,13775.86
NetC6_1 on TOP "TOP-N02399" (solid, pour order 36): 10515.72,12870.86 10452.43,12807.58 10472.43,12787.58 10535.72,12850.86 10515.72,12870.86
NetG1_1 on TOP "TOP-N48428" (solid, pour order 31): 11400.72,13245.86 11400.72,13085.86 11560.72,13085.86 11560.72,13245.86 11400.72,13245.86
NetC1_2 on TOP "TOP-N30996" (solid, pour order 28): 11780.72,12960.86 11780.72,13190.86 11805.72,13215.86 11830.72,13215.86 11860.72,13185.86 11860.72,13000.86 11885.72,12975.86 12015.72,12975.86 12050.72,12940.86 12050.72,12910.86 12020.72,12880.86 11860.72,12880.86 11805.72,12825.86 11805.72,12695.86 11780.72,12670.86 11760.72,12670.86 11720.72,12710.86 11720.72,12900.86 11780.72,12960.86
NetC1_1 on TOP "TOP-N31178" (solid, pour order 27): 11225.72,13770.86 11225.72,12940.86 11425.72,12740.86 11425.72,12705.86 11450.72,12680.86 11475.72,12680.86 11505.72,12710.86 11505.72,12775.86 11310.72,12970.86 11310.72,13775.86 11290.72,13795.86 11250.72,13795.86 11225.72,13770.86
NetD1_3 on TOP "TOP-N53851" (solid, pour order 26): 10950.72,11970.86 11050.72,11870.86 11310.72,11870.86 11420.72,11980.86 11420.72,12005.86 11400.72,12025.86 11360.72,12025.86 11265.72,11930.86 11090.72,11930.86 11000.72,12020.86 10975.72,12020.86 10950.72,11995.86 10950.72,11970.86
NetC12_1 on TOP "TOP-N53822" (solid, pour order 30): 11100.72,12140.86 11100.72,12110.86 11165.72,12045.86 11200.72,12045.86 11230.72,12075.86 11230.72,12140.86 11495.72,12405.86 11495.72,12450.86 11475.72,12470.86 11430.72,12470.86 11100.72,12140.86
VCC_300V on TOP "TOP-No Net 5" (solid, pour order 48): 10875,12655 10830,12655 10805,12680 10805,12710 10870,12775 11035,12775 11055,12795 11055,12870 11005,12920 11005,12975 10949.39,13030.61 10949.39,13043.03 10991.36,13085 11015,13085 11105,12995 11105,12910 11145,12870 11145,12790 11230,12705 11230,12480 11005.72,12255.86 10949.14,12255.86 10880,12325 10880.72,12325.72 10880.72,12355.86 10900,12375 10925,12375 10940,12360 10975,12360 11120,12505 11120,12585 11005,12700 10920,12700
GND_HV on TOP "TOP-No Net 4" (solid, pour order 43): 10120,11910 10120,11945 10305,12130 10350,12130 10480,12000 10495,12005 10595,12105 10630,12105 10675,12150 10675,12260 10535,12400 10535,12430 10565,12460 10680,12460 10785,12355 10785,12260 10860,12185 10860,12150 10510,11800 10275,11800
GND on BOTTOM "BOTTOM-No Net 3" (solid, pour order 41): 9870.1,12375.87 9795.1,12375.87 9705.1,12465.87 9680.1,12520.87 9625.1,12735.87 9625,13055 9650,13080 9782.67,13080 9790,13065 9790,12955 9805,12940 10085,12940 10190,13045 10190,13290 10265,13365 10355,13365 10425,13435 10730,13435 10795,13370 10795,13195 10570,12970 10465,12970
GND_HV on BOTTOM "BOTTOM-No Net 4" (solid, pour order 44): 10700,12430 10825,12305 10885,12305 10925,12345 10940,12345 10950,12335 10950,12325 10865,12240 10825,12240 10795,12210 10755,12210 10725,12180 10695,12210 10695,12250 10625,12320 10625,12355
VDD_3V3_MAIN on BOTTOM "BOTTOM-No Net 1" (solid, pour order 39): 9645,12805 9770,12805 9794.22,12781.5 9985,12780 9995,12770 9995,12685 9960,12650 9665,12650 9635,12680 9635,12795
GND_485_SHIELD on BOTTOM "BOTTOM-No Net" (solid, remove dead copper, pour order 32): 10154.23,13036.4 10175,13057.17 10175,13290 10260,13375 10350,13375 10450,13475 10450,13785 10435,13800 10380,13800 10360,13780 10360,13480 10315,13435 10210,13435 10030,13255 9980,13255 9980,12950 10080,12950 10154.23,13034.23
VDD_5V_MAIN on BOTTOM "BOTTOM-No Net 2" (solid, pour order 40): 9885,12365 10470,12950 10520,12950 10560,12910 10560,12835 10015,12290 9910,12290 9885,12330
NetC10_2 on BOTTOM "BOTTOM-No Net 5" (solid, pour order 45): 10715,12430 10715,12440 10800,12525 10840,12525 10875,12490 10875,12470.01 10830,12425.01 10830,12403.15 10860,12373.15 10860,12360 10830,12330 10815,12330
VCC_300V on BOTTOM "BOTTOM-No Net 7" (solid, pour order 47): 10180,12110 10240,12110 10260,12130 10265,12245 10700,12680 10805,12680 10830,12655 10860,12655 10860,12655.08 10895,12690.08 10895,12730 10825,12800 10760,12800 10165,12205 10165,12125
NetC10_1 on BOTTOM "BOTTOM-No Net 6" (solid, pour order 46): 10670,12540 10670,12580 10700,12610 10880,12610 10935,12555 10935,12540 10915,12520 10890,12520 10850,12560 10770,12560 10730,12520 10690,12520

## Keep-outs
Keep-Out Layer:
  circle w1: c10870,12895 r1653.54
  circle w1: c10013.7,14145 r98.43
  circle w1: c10870,14076.1 r227.35
  circle w1: c11726.3,14145 r98.43
  circle w1: c9797.17,11822.16 r98.43
  circle w1: c10870,11713.9 r227.35
  circle w1: c11942.84,11822.16 r98.43
  lines w1: 10973.14,13115 10012.36,12154.22 cw(c9998.22,12168.36) 9984.07,12182.5 10946.57,13145 cw(c10960.71,13130.86) 10974.85,13116.72

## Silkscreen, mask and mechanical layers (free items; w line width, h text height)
Top Overlay:
  lines w5: 10308.07,11768.69 ccw(c10343.24,11839.13) 10419.3,11818.75 10420.09,11821.69 cw(c10819.39,11714.7) 10819.39,12128.08 10902.09,12128.08 cw(c10902.09,11714.7) 11301.39,11821.69 11304.54,11809.94 ccw(c11380.6,11830.32) 11414.57,11759.29 ; 10327.58,11759.15 cw(c10870.93,12895.8) 11399.73,11752.31
  lines w10: 9932.5,12632.5 9835,12535 9835,12515 9987.43,12362.57 9987.43,12387.57 9965.96,12366.11 9971.33,12366.11 9982.06,12366.11 9987.43,12366.11
Bottom Overlay:
  lines w5: 9260,13265 12480,13265.94
  lines w10: 10815,12290 11015,12090 ; 11015,12090 10990,12090 11010,12110 11015,12110 ; 11015,12090 11011.58,12093.42 10998.42,12093.42 11015,12110 ; 11015,12090 11015,12110
NCLEGEND-1-2:
  circle w1: c13110.22,12742.36 r15.75
  circle w1: c13110.22,12461.36 r16
  circle w1: c13110.22,12180.36 r19.68
  lines w1: 12660.72,11758.86 17496.72,11758.86 ; 12660.72,12039.86 17496.72,12039.86 ; 12660.72,12320.86 17496.72,12320.86 ; 12660.72,12601.86 17496.72,12601.86 ; 12660.72,12882.86 17496.72,12882.86 ; 12660.72,13163.86 17496.72,13163.86 ; 12660.72,13444.86 17496.72,13444.86 ; 12660.72,13725.86 17496.72,13725.86 ; 13100.22,13023.36 13120.22,13023.36 ; 13110.22,13013.36 13110.22,13033.36 ; 13559.72,11477.86 13559.72,13444.86 ; 15450.72,11477.86 15450.72,13444.86 ; 16721.72,11477.86 16721.72,13444.86 ; 12660.72,11477.86 12660.72,13975.86 17496.72,13975.86 17496.72,11477.86 12660.72,11477.86 ; 13110.22,11844.26 cw(c13110.22,11899.36) 13110.22,11954.46 cw(c13110.22,11899.36) 13110.22,11844.26
  text "DRILL CHART: TOP to BOTTOM" at 13778.72,13788.36 h125
  text "ALL UNITS ARE IN MILS" at 14028.72,13538.36 h125
  text "FIGURE" at 12810.22,13257.36 h125
  text "SIZE" at 14305.22,13257.36 h125
  text "PLATED" at 15786.22,13257.36 h125
  text "QTY" at 16959.22,13257.36 h125
  text "16.0" at 14305.22,12960.86 h125
  text "PLATED" at 15786.22,12960.86 h125
  text "9" at 17059.22,12960.86 h125
  text "31.4961" at 14155.22,12679.86 h125
  text "PLATED" at 15786.22,12679.86 h125
  text "18" at 17009.22,12679.86 h125
  text "32.0" at 14305.22,12398.86 h125
  text "PLATED" at 15786.22,12398.86 h125
  text "8" at 17059.22,12398.86 h125
  text "39.3701" at 14155.22,12117.86 h125
  text "PLATED" at 15786.22,12117.86 h125
  text "12" at 17009.22,12117.86 h125
  text "39.3701" at 14155.22,11836.86 h125
  text "PLATED" at 15786.22,11836.86 h125
  text "8" at 17059.22,11836.86 h125
  text "PLATED" at 15786.22,11555.86 h125
  text "4" at 17059.22,11555.86 h125
OUTLINE:
  circle w1: c10870.72,14076.96 r227.35
  circle w1: c10870.72,12895.86 r1653.54
  circle w1: c11943.55,11823.03 r98.43
  circle w1: c11727.02,14145.86 r98.43
  circle w1: c10014.42,14145.86 r98.43
  circle w1: c9797.88,11823.03 r98.43
  circle w1: c10870.72,11714.76 r227.35
DRAWING_ORIGIN:
  lines w1: 10845.72,12895.86 10895.72,12895.86 ; 10870.72,12870.86 10870.72,12920.86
